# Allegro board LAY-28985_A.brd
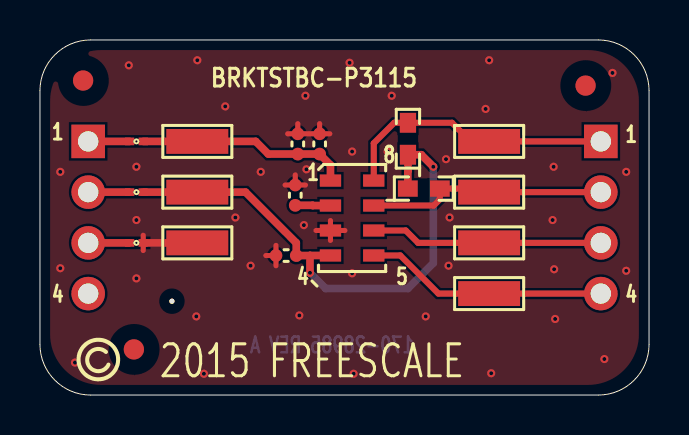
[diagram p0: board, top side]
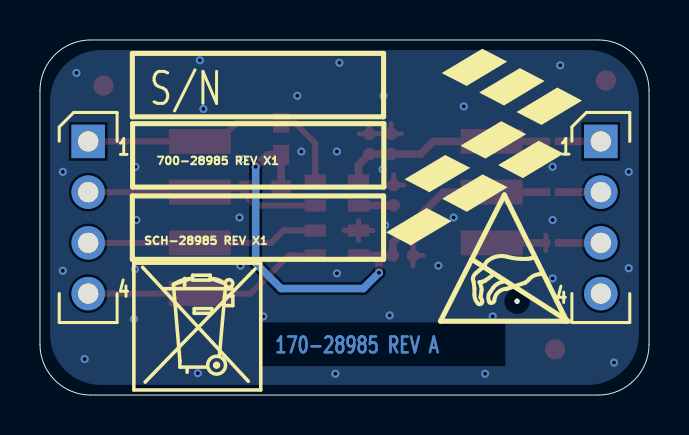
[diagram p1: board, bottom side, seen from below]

Outline 30.48 x 17.78 mm; copper layers: TOP, BOTTOM. Coordinates in mm from the lower left corner of the outline.
Outline path: 0,15.24 0,2.54 arc(0.74,0.74) 2.54,0 27.94,0 arc(29.74,0.74) 30.48,2.54 30.48,15.24 arc(29.74,17.04) 27.94,17.78 2.54,17.78 arc(0.74,17.04) 0,15.24

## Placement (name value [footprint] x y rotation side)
C1  10uF  [CC0402_25]  14 12.57 90 top
C2  0.1UF  [CC0402_25]  12.9 12.57 90 top
C3  0.1UF  [CC0402_25]  12.32 6.98 180 top
C4  0.1UF  [CC0402_25]  12.78 10.01 90 top
GND1  0805  [TESTPOINT_122X049MIL]  7.87 7.62 180 top
INT1  0805  [TESTPOINT_122X049MIL]  22.48 7.62 0 top
INT2  0805  [TESTPOINT_122X049MIL]  22.48 5.08 0 top
J1  HDR 1X4  [HDR104]  2.41 12.7 180 bottom
J2  HDR 1X4  [HDR104]  28.07 12.7 180 bottom
NOREF  -  []  5.71 -0.7 0 top
NOREF#2  -  []  22.72 -0.7 0 top
NOREF#3  -  []  17.61 0 90 top
NOREF#4  -  []  0 16.25 0 top
NOREF#5  -  [unnamed#2]  2.16 15.75 180 top
NOREF#6  -  []  22.72 0.59 90 top
NOREF#7  -  []  16.54 12.47 90 top
NOREF#8  -  [unnamed#2]  4.7 2.29 180 top
NOREF#9  -  []  15.54 12.69 90 top
NOREF#10  -  []  8.87 9.53 90 top
NOREF#11  -  []  5.71 17.08 0 top
NOREF#12  -  []  25.48 10.79 90 top
NOREF#13  -  []  22.72 -4.49 90 top
NOREF#14  -  []  22.72 6.92 0 top
NOREF#15  -  []  22.72 13.29 90 top
NOREF#16  -  []  22.72 14.54 0 top
NOREF#17  -  []  5.71 -4.49 90 top
NOREF#18  -  []  22.72 8.21 90 top
NOREF#19  -  []  29.81 18.18 0 top
NOREF#20  -  []  22.72 -1.95 90 top
NOREF#21  -  []  16.52 15.47 0 top
NOREF#22  -  []  23.48 4.45 90 top
NOREF#23  -  [unnamed#2]  27.3 15.49 180 top
NOREF#24  -  []  5.71 9.46 0 top
NOREF#25  -  []  5.71 3.13 90 top
NOREF#26  -  []  13.76 12.97 0 top
NOREF#27  -  []  5.71 13.29 90 top
NOREF#28  -  []  -284.73 256.54 0 top
NOREF#29  -  []  8.87 8.25 0 top
NOREF#30  -  []  5.71 15.83 90 top
NOREF#31  -  []  -310.77 -268.6 0 top
NOREF#32  -  []  22.72 3.13 90 top
NOREF#33  -  []  22.72 -3.24 0 top
NOREF#34  -  []  5.71 0.59 90 top
NOREF#35  -  []  22.72 10.75 90 top
NOREF#36  -  []  22.72 15.83 90 top
NOREF#37  -  []  6.87 9.53 0 top
NOREF#38  -  []  14.54 12.69 90 top
NOREF#39  -  []  22.72 1.84 0 top
NOREF#40  -  []  5.71 6.92 0 top
NOREF#41  -  []  3.05 1.91 0 top
NOREF#42  -  []  5.71 -1.95 90 top
NOREF#43  -  []  5.71 5.67 90 top
NOREF#44  -  []  22.72 12 0 top
NOREF#45  -  []  8.87 12.07 90 top
NOREF#46  -  []  297.56 -45.09 0 top
NOREF#47  -  []  5.71 14.54 0 top
NOREF#48  -  []  23.48 6.99 90 top
NOREF#49  -  []  23.48 10.79 0 top
NOREF#50  -  []  5.71 12 0 top
NOREF#51  -  []  5.71 -3.24 0 top
NOREF#52  -  []  16.31 12.97 90 top
NOREF#53  -  []  22.72 9.46 0 top
NOREF#54  -  []  21.48 4.45 0 top
NOREF#55  -  []  -12.95 -55.88 0 top
NOREF#56  -  []  5.71 8.21 90 top
NOREF#57  -  []  6.87 12.07 0 top
NOREF#58  -  []  21.48 6.99 0 top
NOREF#59  -  []  5.71 1.84 0 top
NOREF#60  -  []  22.72 17.08 0 top
NOREF#61  -  []  5.71 4.38 0 top
NOREF#62  -  []  10.87 8.25 90 top
NOREF#63  -  [unnamed#2]  6.6 4.7 180 top
NOREF#64  -  []  14.54 12.69 0 top
NOREF#65  -  []  22.72 5.67 90 top
NOREF#66  -  []  16.31 12.97 90 top
NOREF#67  -  []  16.31 12.97 90 top
NOREF#68  -  []  22.72 4.38 0 top
NOREF#69  -  []  13.54 12.47 0 top
NOREF#70  -  []  23.48 13.33 0 top
NOREF#71  -  []  25.48 13.33 90 top
NOREF#72  -  []  5.71 10.75 90 top
NOREF#73  -  []  13.16 7.49 180 bottom
NOREF#74  -  []  25.86 6.79 180 bottom
NOREF#75  -  []  25.86 13.93 180 bottom
NOREF#76  -  []  1.78 10.81 180 bottom
NOREF#77  -  []  25.78 0.25 180 bottom
NOREF#78  -  []  25.84 10.41 180 bottom
R1  4.7K  [RC0603]  19.21 10.34 0 top
R2  4.7K  [RC0603]  18.41 12.83 90 top
SCL1  0805  [TESTPOINT_122X049MIL]  22.48 12.7 180 top
SDA1  0805  [TESTPOINT_122X049MIL]  22.48 10.16 180 top
SH1  0  [SH0201]  4.83 12.7 0 top
SH2  0  [SH0201]  4.83 10.16 0 top
SH3  0  [SH0201]  4.82 7.62 180 top
U1  MPL3115A2  [LGA8_1P25_3X5_0P5]  15.62 8.86 0 top
VDD_3115  0805  [TESTPOINT_122X049MIL]  7.87 12.7 0 top
VDDIO_3115  0805  [TESTPOINT_122X049MIL]  7.87 10.16 0 top

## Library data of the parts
C1-C4 = CAP_NP
GND1 INT1 INT2 SCL1 SDA1 VDD_3115 VDDIO_3115 = TEST_POINT
J1 J2 = CONN_HDR_4X1
R1 R2 = RES
SH1-SH3 = RES_SHORT-2: Tolerance: TOLERANCE; User Part Number: 470-76473
U1 = PPL3115A2_LGA_8P

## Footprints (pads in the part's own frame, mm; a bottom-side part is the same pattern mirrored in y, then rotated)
CC0402_25
  round 0.635 smd: 1(-0.508,0) 2(0.508,0)
HDR104
  rect 1.676x1.676 hole 1.016: 1(0,0)
  round 1.676 hole 1.016: 2(0,-2.54) 3(0,-5.08) 4(0,-7.62)
LGA8_1P25_3X5_0P5
  rect 1.067x0.61 smd: 1(-1.083,1.875) 2(-1.083,0.625) 3(-1.083,-0.625) 4(-1.083,-1.875) 5(1.083,-1.875) 6(1.083,-0.625) 7(1.083,0.625) 8(1.083,1.875)
RC0603
  rect 0.991x0.813 smd: 1(-0.8,0) 2(0.8,0)
SH0201
  rect 0.47x0.381 smd: 1(-0.343,0) 2(0.343,0)
TESTPOINT_122X049MIL
  rect 3.099x1.245 smd: 1(0,0)
unnamed#2
  round 1.016 smd: (0,0)

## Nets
GND: C1.2 C2.2 C3.2 C4.2 GND1.1 SH3.1 U1.3(GND)
GND_1: J1.3 SH3.2
VDD: C1.1 C2.1 SH1.2 U1.1(VDD) VDD_3115.1
VDD_1: J1.1 SH1.1
VDDIO: C3.1 R1.1 R2.1 SH2.2 U1.4(VDDIO) VDDIO_3115.1
VDDIO_1: J1.2 SH2.1
INT_1: INT1.1 J2.3 U1.6(INT1)
INT_2: INT2.1 J2.4 U1.5(INT2)
NC1: J1.4
SCL_1: J2.1 R2.2 SCL1.1 U1.8(SCL)
SDA_1: J2.2 R1.2 SDA1.1 U1.7(SDA)
N16859277: C4.1 U1.2(CAP)

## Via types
v1: diameter 0.406, hole 0.203, TOP to BOTTOM, 41 vias

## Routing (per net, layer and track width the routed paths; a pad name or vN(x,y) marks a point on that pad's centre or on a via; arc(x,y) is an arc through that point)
GND: length 12
  TOP w0.254: 13.49,13.08 C1.2 ; C1.2 14.5,13.08 ; C1.2 14,13.59 ; 12.27,10.52 C4.2 ; C4.2 12.78,11.02 ; C4.2 13.28,10.52 ; C3.2 11.81,7.49 ; C3.2 11.81,6.48 ; C3.2 11.3,6.98 ; C2.2 12.9,13.59 ; C2.2 13.41,13.08 ; C2.2 12.39,13.08 ; U1.3 14.54,8.74 ; U1.3 15.26,8.24 ; U1.3 13.81,8.24 ; U1.3 14.54,7.74 ; 5.17,8 SH3.1 5.17,7.24
  TOP w0.381: SH3.1 GND1.1
  vias: v1(1.02,11.18) v1(1.02,6.35) v1(1.75,1.63) v1(4.45,16.51) v1(4.83,11.43) v1(4.83,8.76) v1(4.83,5.84) v1(7.82,3.94) v1(7.87,16.76) v1(8.2,1.07) v1(9.27,14.45) v1(9.78,8.89) v1(10.54,6.48) v1(11.05,11.18) v1(12.98,3.99) v1(13.21,8.51) v1(13.28,14.99) v1(13.33,11.3) v1(15.49,16.64) v1(15.62,12.19) v1(15.62,6.1) v1(15.7,1.07) v1(17.4,12.19) v1(17.6,14.99) v1(19.3,3.94) v1(20.32,11.81) v1(20.45,6.48) v1(20.5,8.89) v1(22.3,14.33) v1(22.48,16.76) v1(22.58,1.09) v1(25.7,11.43) v1(25.65,8.76) v1(25.73,6.3) v1(25.78,3.81) v1(28.24,1.8) v1(28.65,16.13) v1(29.34,11.18) v1(29.34,6.22)
GND_1: length 2.1
  TOP w0.381: J1.3 SH3.2
VDD: length 10.6
  TOP w0.381: U1.1 14.54,11.52 C1.1 C2.1 11.43,12.06 10.79,12.7 VDD_3115.1 SH1.2
VDD_1: length 2.1
  TOP w0.381: J1.1 SH1.1
VDDIO: length 27
  TOP w0.381: SH2.2 VDDIO_3115.1 10.29,10.16 12.83,7.62 C3.1 13.51,6.98 ; v1(19.69,11.43) 19.08,12.03 R2.1 18.41,11.22 18.41,11.21 R1.1 ; 13.51,6.98 v1(13.51,6.12) ; 13.51,6.98 13.52,6.99 U1.4
  BOTTOM w0.381: v1(19.69,11.43) 19.69,6.6 18.41,5.33 14.3,5.33 v1(13.51,6.12)
VDDIO_1: length 2.1
  TOP w0.381: J1.2 SH2.1
INT_1: length 11.6
  TOP w0.305: U1.6 18.3,8.24 18.92,7.62 INT1.1 J2.3
INT_2: length 12.2
  TOP w0.305: U1.5 18.03,6.99 19.94,5.08 INT2.1 J2.4
SCL_1: length 14
  TOP w0.305: U1.8 16.7,12.61 17.73,13.63 R2.2 20.62,13.63 21.55,12.7 SCL1.1 J2.1
SDA_1: length 12.1
  TOP w0.305: J2.2 SDA1.1 22.3,10.34 R1.2 20.01,9.79 19.7,9.49 U1.7
N16859277: length 1.8
  TOP w0.381: C4.1 13.64,9.5 13.65,9.49 U1.2

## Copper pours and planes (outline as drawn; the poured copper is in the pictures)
GND on TOP, BOTTOM: 3.05,0.51 1.25,1.25 0.51,3.05 0.51,14.73 1.25,16.53 3.05,17.27 27.43,17.27 29.23,16.53 29.97,14.73 29.97,3.05 29.23,1.25 27.43,0.51

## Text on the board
BOTTOM: 170-28985 REV A | 5 OF 8 | L2_SS
Board Geometry/Soldermask Bottom: 6 OF 8 | SECONDARY SOLDERMASK
Ref Des/Silkscreen Bottom: 7 OF 8 | SECONDARY SILKSCREEN
User.Comments: 17 | 1 OF 1 | TEST PROBE | 1/1 | 1
TOP: 4 OF 8 | L1_PS
Board Geometry/Soldermask Top: 3 OF 8 | PRIMARY SOLDERMASK
Ref Des/Silkscreen Top: BRKTSTBC-P3115 | 2 OF 8 | PRIMARY SILKSCREEN
DIMENSION: (X4) | 0.062" THICK +/-10%
BODY_CENTER: 8 | SH3  GND_1 & GND | SH1  VDD_1 & VDD | 22. INTENTIONAL SHORTS AT: | SH2  VDDIO_1 & VDDIO
PASTEMASK_TOP: 1 OF 8 | PASTEMASK TOP
User.5: 8 OF 8 | SECONDARY PASTEMASK
User.16: FIGURE | SIZE | 8.0 | 40.0 | 25.0 | DRILL CHART: TOP to BOTTOM | ALL UNITS ARE IN MILS | TOLERANCE | +0.0/-8.0 | +3.0/-3.0 | +2.0/-2.0 | PLATED | NON-PLATED | QTY | 41 | 8 | 1
